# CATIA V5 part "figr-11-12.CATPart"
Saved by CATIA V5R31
Part number: Part1
Bounding box of the stored display mesh (mm): x -10 to 5, y -10.258 to 7.91, z -1.851 to 2.054
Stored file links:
  D:\PROJECTS\Project 2021\US EDITION\CATIA V5 6R 2021\Resources\Part Files\c11_catia_v5_6r2021_prt\figr-11-12.CATPart
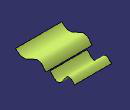
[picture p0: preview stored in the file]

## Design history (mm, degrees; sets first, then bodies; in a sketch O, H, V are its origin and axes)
Set1
  Sketch1 on yz-plane, origin (0, 0, 0), H (0, 1, 0), V (0, 0, 1)
    spline S1 through (-0.358, 0) (-3.1664, 2.0538) (-6.7822, 0.4079) (-10.2576, 1.6423)
    point P1 (-0.358, 0)
    coincidence: P1 H
  Extrude1: Element1 Sketch1, Lim1 5, Lim2 10, Direction yz-plane
  Sketch2 on yz-plane, origin (0, 0, 0), H (0, 1, 0), V (0, 0, 1)
    spline S1 through (0, 0) (3.5471, -1.4404) (5.7957, 1.2855) (7.9098, 0)
    point P1 (0, 0)
    point P2 (7.9098, 0)
    coincidence: P1 O, P2 H
  Extrude2: Element1 Sketch2, Lim1 4, Lim2 8, Direction yz-plane
Body1 (main body)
